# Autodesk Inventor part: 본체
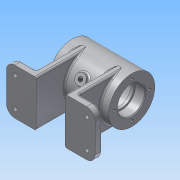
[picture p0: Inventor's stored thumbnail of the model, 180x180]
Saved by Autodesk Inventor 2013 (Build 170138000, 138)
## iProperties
Created: 2017-02
Part Number: 본체
Material: 알루미늄 6061
Document SubType Name: Modeling
Designer: Administrator
Density: 2.71 g/cm^3
Mass: 355.548 g
Surface Area: 423.192 cm^2
Volume: 131.199 cm^3
Author: Administrator
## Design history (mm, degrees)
sketch "스케치1"
  geometry: L1 (-35, 27)-(35, 27); L2 (35, 27)-(35, 16); L3 (35, 0)-(-35, 0); L4 (-35, 16)-(-23, 16); L5 (-23, 16)-(-23, 14); L6 (-23, 14)-(-20, 14); L7 (-20, 14)-(-20, 22); L8 (-20, 22)-(20, 22); L9 (20, 22)-(20, 14); L10 (20, 14)-(23, 14); L11 (23, 14)-(23, 16); L12 (23, 16)-(35, 16); L13 (-35, 16)-(-35, 27); 2 further points
  constraints: 26 end point, 9 parallel, 2 perpendicular, 1 coincident, 1 collinear, 1 midpoint, 1 vertical
  dimensions: "d0" = 70 distance of L1.start L1.end; "d2" = 27 distance of L1.end L3.start; "d3" = 40 distance of L7.end L8.end; "d4" = 12 distance of L4.start L4.end; "d5" = 12 distance of L11.end L2.end; "d6" = 3 distance of L5.end L6.end; "d7" = 44 diameter of L8 L3; "d8" = 32 diameter of L12 L3; "d9" = 32 diameter of L4 L3; "d10" = 28 diameter of L6 L3; "d11" = 28 diameter of L10 L3; "d12" = 70 distance of L3.start L3.end; "d13" = 16 distance of L3.start L2.end
revolve "회전1" sketch "스케치1" stored, may be unused: angle "d14" = 90 deg
fillet "모깎기1" dims "d15" = 0.3
chamfer "모따기1" distance "d16" = 1; stored, may be unused: second distance "d17" = 2, angle "d18" = 45 deg
node "작업 평면1"
sketch "스케치2"
  geometry: L1 (-52, 27)-(-52, -27); L2 (-52, -27)-(-17, -27); L3 (-17, -27)-(-17, 27); L4 (-17, 27)-(-52, 27); L5 (17, 27)-(17, -27); L6 (17, -27)-(52, -27); L7 (52, -27)-(52, 27); L8 (52, 27)-(17, 27); 1 further point
  constraints: 16 end point, 4 vertical, 2 horizontal, 2 perpendicular, 1 collinear
  dimensions: "d21" = 54 distance of L1.start L1.end; "d23" = 54 distance of L5.start L5.end; "d24" = 35 distance of L3.end L1.start; "d25" = 35 distance of L7.end L5.start; "d26" = 17 distance from line of point (0, 0) L3; "d27" = 17 distance from line of L5 point (0, 0); "d28" = 27 distance from line of point (0, 0) L2
extrude "돌출1" join sketch "스케치2" distance "d29" = 8; taper "d30" = 0 deg
fillet "모깎기2" dims "d31" = 10
sketch "스케치3"
  geometry: L1 (-42, -27)-(-17, -27) reference; L2 (-17, -27)-(-17, 27) reference; L3 (-17, 27)-(-42, 27) reference; L4 (-25, 27)-(-25, -27); L5 (25, 27)-(25, -27); L6 (17, 27)-(17, -27) reference; L7 (-17, -27)-(-17, 27) reference; L8 (-17, 27)-(-42, 27) reference; L9 (-42, -27)-(-17, -27) reference; L10 (17, -27)-(42, -27) reference; L11 (42, 27)-(17, 27) reference; L12 (-25, 27)-(-17, 27); L13 (-17, -27)-(-25, -27); L14 (25, -27)-(17, -27); L15 (17, 27)-(25, 27); 1 further point
  constraints: 12 end point, 3 collinear, 2 parallel, 2 point on line, 1 perpendicular
  dimensions: "d32" = 8 distance between parallel lines of L2 L4; "d33" = 8 distance between parallel lines of L6 L5
extrude "돌출2" join sketch "스케치3" stored distance "d34" = 8; taper "d35" = 0 deg
sketch "스케치4"
  geometry: L1 (-25, 27)-(-42, 27) reference; L2 (-52, 17)-(-52, -17) reference; 3 further points
  dimensions: "d36" = 34 distance of point (-42, -17) point (-42, 17); "d38" = 10 distance from line of L1 point (-42, 17); "d39" = 10 distance from line of L2 point (-42, 17); "d40" = 10 distance from line of L2 point (-42, -17)
hole "구멍1" sketch "스케치4" at (-42, -17), (-42, 17) diameter "d41" = 5; stored, may be unused: countersink angle "d45" = 90 deg, drill point angle "d47" = 118 deg; dims "d42" = 6, "d43" = 3, "d44" = 2, "d46" = 8
fillet "모깎기3" dims "d59" = 2
sketch "스케치6"
  geometry: C1 r 27 at (0, 0) reference; 4 further points
  constraints: 2 horizontal alignment, 2 vertical alignment
  dimensions: "d60" = 21 distance of C1.centre point (0, 21); "d61" = 21 distance of point (0, -21) C1.centre; "d62" = 21 distance of point (21, 0) C1.centre; "d63" = 21 distance of point (-21, 0) C1.centre
hole "구멍2" sketch "스케치6" at (0, 21), (-21, 0), (0, -21), (21, 0) diameter "d64" = 3.242; stored, may be unused: countersink angle "d68" = 90 deg, drill point angle "d70" = 118 deg; dims "d65" = 8, "d66" = 4, "d67" = 2, "d69" = 10
node "작업 평면2"
sketch "스케치7"
  geometry: L1 (-35, 27)-(-35, -27) reference; C1 r 5 at (-10, 0); 1 further point
  constraints: 1 centre point, 1 horizontal alignment
  dimensions: "d71" = 10 diameter of C1; "d72" = 25 distance from line of C1.centre L1
extrude "돌출4" join sketch "스케치7" distance "d73" = 5; taper "d75" = 0 deg; dims "d74" = 3, "d76" = 0
fillet "모깎기4" dims "d77" = 2
sketch "스케치8"
  geometry: C1 r 5 at (0, 0) reference; 2 further points
  constraints: 1 coincident
hole "구멍3" sketch "스케치8" at (0, 0) diameter "d78" = 5.188; stored, may be unused: countersink angle "d82" = 90 deg, drill point angle "d84" = 118 deg; dims "d79" = 6, "d80" = 4, "d81" = 2, "d83" = 10
sketch "스케치9"
  geometry: L1 (0, 0)-(-25.16, 16.339); L2 (0, 0)-(-26.936, 0)
  constraints: 4 end point, 1 horizontal
  dimensions: "d85" = 33 deg angle of L2 L1; "d86" = 30 distance of L1.start L1.end; "d87" = 26.93621 distance of L1.start L2.end
node "작업 평면3"
sketch "스케치10"
  geometry: L1 (30, 0)-(30, 6); L2 (30, 6)-(24, 6); L3 (24, 6)-(24, 0); L4 (24, 0)-(30, 0); 1 further point
  constraints: 8 end point, 1 parallel, 1 perpendicular, 1 vertical
  dimensions: "d89" = 6 distance of L1.start L1.end; "d90" = 6 distance of L1.end L2.end; "d91" = 6 distance of L2.end L3.end; "d92" = 6 distance of L3.end L1.start (derived)
revolve "회전2" sketch "스케치10" stored, may be unused: angle "d93" = 90 deg
sketch "스케치11"
  geometry: C1 r 6 at (0, 0) reference; 1 further point
  constraints: 1 coincident
hole "구멍4" sketch "스케치11" at (0, 0) diameter "d94" = 5.188; stored, may be unused: countersink angle "d98" = 90 deg, drill point angle "d100" = 118 deg; dims "d95" = 6, "d96" = 4, "d97" = 2, "d99" = 10
fillet "모깎기5" dims "d101" = 3
fillet "모깎기6" dims "d102" = 2
node "작업 평면4"
sketch "스케치12"
  geometry: L1 (35, 27)-(-35, 27) reference; L2 (-35, 27)-(-35, -27) reference; 2 further points
  constraints: 1 other
  dimensions: "d103" = 0 distance of point (0, 0) point (0, 0); "d104" = 35 distance from line of L2 point (0, 0)
feature "엠보싱1" sketch "스케치12" dims "d0" = 70, "d2" = 27, "d3" = 40, "d4" = 12, "d5" = 12, "d6" = 3, "d7" = 44, "d8" = 32, "d9" = 32, "d10" = 28, "d11" = 28, "d12" = 70, "d13" = 16, "d16" = 1, "d105" = 0.5, "d106" = 0
sketch "스케치13"
  geometry: L1 (-39.113, 22)-(-36.226, 17); L2 (-36.226, 17)-(-39.113, 12); L3 (-39.113, 12)-(-44.887, 12); L4 (-44.887, 12)-(-47.774, 17); L5 (-47.774, 17)-(-44.887, 22); L6 (-44.887, 22)-(-39.113, 22); C1 r 2.5 at (-42, 17) reference; 2 further points
  constraints: 12 end point, 1 coincident, 1 horizontal, 13 other
  dimensions: "d109" = 5 distance from line of point (-42, 17) L6
extrude "돌출5" cut sketch "스케치13" distance "d110" = 3; taper "d111" = 0 deg
node "솔리드1"
mirror "대칭1"
mirror "대칭2"
pattern_linear "직사각형 패턴2" dims "d114" = 34, "d117" = 84
other parameters: "d88" = 90 deg
